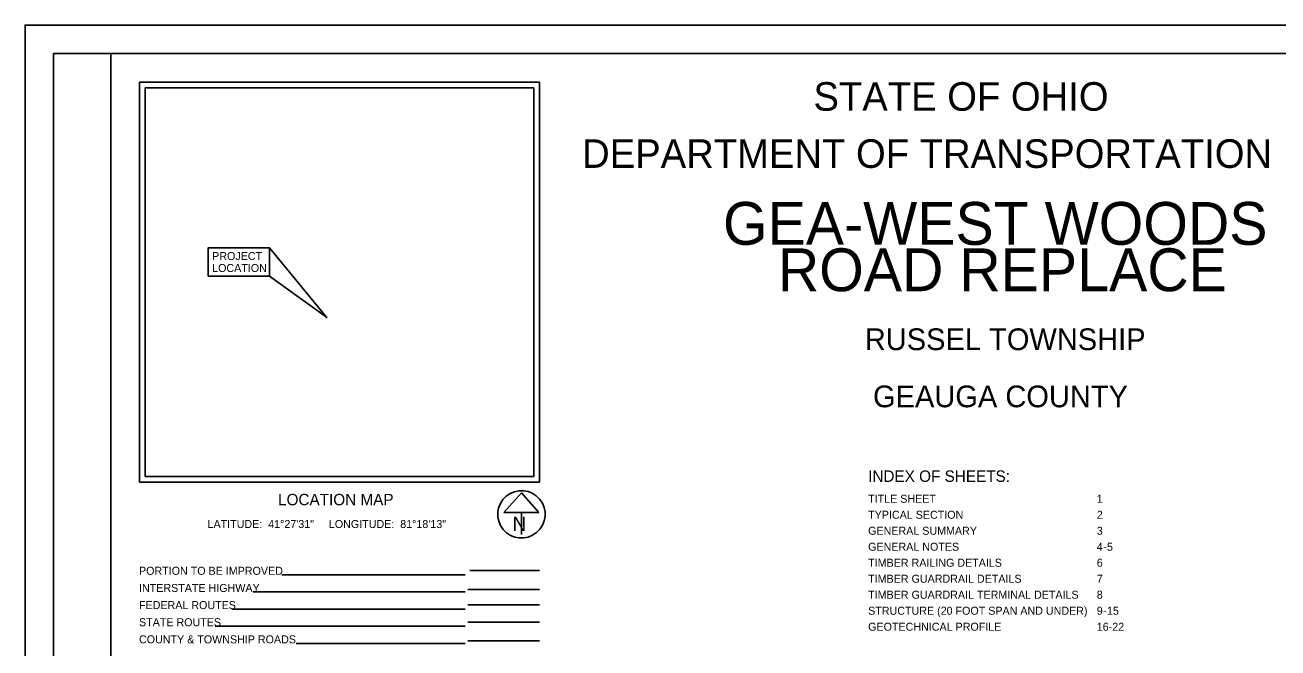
# Model space of a CAD drawing. Extents: x 0 to 81.5, y 0 to 35.2.
# Drawn here: x 0 to 21.92, y 11.1 to 22 of the extents above; entities that cross this region are included whole.
import ezdxf

# ---------------------------------------------------------------- set-up
doc = ezdxf.new("R2010")
doc.units = 0
for name, color, linetype in [('Default', 7, 'Continuous'), ('SH_Border', 7, 'Continuous'), ('SH_Cut_Line', 7, 'Continuous'), ('SH_Data', 7, 'Continuous'), ('SH_Text', 7, 'Continuous')]:
    doc.layers.add(name, color=color, linetype=linetype)

msp = doc.modelspace()

# ---------------------------------------------------------------- linework, layer by layer
at = {"layer": 'Default'}
for points in [[(3.204, 17.602), (4.276, 17.602), (4.276, 18.102), (3.204, 18.102)], [(4.276, 18.102), (5.277, 16.884), (4.276, 17.602)]]:
    msp.add_lwpolyline(points, close=True, dxfattribs=at)
at = {"layer": 'SH_Border'}
for points in [[(0.5, 21.5), (1.5, 21.5), (1.5, 0.5), (0.5, 0.5)], [(1.5, 21.5), (33.5, 21.5), (33.5, 0.5), (1.5, 0.5)]]:
    msp.add_lwpolyline(points, close=True, dxfattribs=at)
at = {"layer": 'SH_Cut_Line'}
msp.add_lwpolyline([(0, 0), (34, 0), (34, 22), (0, 22)], close=True, dxfattribs=at)
at = {"layer": 'SH_Data'}
for p, q in [((2, 21), (9, 21)), ((2, 21), (2, 14)), ((2.1, 20.9), (2.1, 14.1)), ((2.1, 20.9), (8.9, 20.9)), ((8.9, 20.9), (8.9, 14.1)), ((9, 21), (9, 14)), ((5.277, 16.9), (5.276, 16.868)), ((2.1, 14.1), (8.9, 14.1)), ((2.1, 14.1), (2.1, 14.1)), ((2, 14), (9, 14)), ((8.685, 13.809), (8.377, 13.468)), ((8.992, 13.468), (8.685, 13.809)), ((8.377, 13.468), (8.992, 13.468)), ((8.685, 13.468), (8.685, 13.081)), ((8.685, 13.435), (8.685, 13.435)), ((8.685, 13.435), (8.685, 13.435)), ((7.7, 12.377), (4.494, 12.377)), ((7.783, 12.455), (9, 12.455)), ((7.7, 12.077), (3.99, 12.077)), ((9, 12.121), (7.75, 12.121)), ((9, 11.849), (7.75, 11.849)), ((7.7, 11.777), (3.619, 11.777)), ((7.7, 11.477), (3.329, 11.477)), ((9, 11.549), (7.75, 11.549)), ((9, 11.222), (7.75, 11.222)), ((7.7, 11.177), (4.745, 11.177))]:
    msp.add_line(p, q, dxfattribs=at)
msp.add_arc((8.685, 13.435), 0.415, 129.7798, 129.7633, dxfattribs=at)

# ---------------------------------------------------------------- texts
at = {"layer": 'Default'}
for s, p in [('PROJECT', (3.274, 17.887)), ('LOCATION', (3.274, 17.677))]:
    msp.add_text(s, height=0.14, dxfattribs=at).set_placement(p)
at = {"layer": 'SH_Data'}
msp.add_text('N', height=0.25, dxfattribs=at).set_placement((8.529, 13.144))
at = {"layer": 'SH_Text'}
for s, height, p in [('STATE OF OHIO', 0.5, (13.795, 20.5)), ('DEPARTMENT OF TRANSPORTATION', 0.5, (9.747, 19.5)), ('GEA-WEST WOODS', 0.75, (12.212, 18.153)), ('ROAD REPLACE', 0.75, (13.171, 17.341)), ('RUSSEL TOWNSHIP', 0.38, (14.693, 16.31)), ('GEAUGA COUNTY', 0.38, (14.837, 15.31)), ('INDEX OF SHEETS:', 0.2, (14.752, 14.004)), ('LOCATION MAP', 0.2, (4.427, 13.594)), ('TITLE SHEET ', 0.14, (14.752, 13.638)), ('1', 0.14, (18.752, 13.638)), ('TYPICAL SECTION ', 0.14, (14.752, 13.358)), ('2', 0.14, (18.752, 13.358)), ('LATITUDE:  41°27\'31"     LONGITUDE:  81°18\'13"', 0.14, (3.193, 13.196)), ('GENERAL SUMMARY ', 0.14, (14.752, 13.078)), ('3', 0.14, (18.752, 13.078)), ('GENERAL NOTES ', 0.14, (14.752, 12.798)), ('4', 0.14, (18.752, 12.798)), ('5', 0.14, (18.931, 12.798)), ('-', 0.14, (18.863, 12.798)), ('PORTION TO BE IMPROVED', 0.14, (1.994, 12.377)), ('TIMBER RAILING DETAILS   ', 0.14, (14.752, 12.518)), ('6', 0.14, (18.752, 12.518)), ('TIMBER GUARDRAIL DETAILS ', 0.14, (14.752, 12.238)), ('7', 0.14, (18.752, 12.238)), ('INTERSTATE HIGHWAY', 0.14, (1.994, 12.077)), ('TIMBER GUARDRAIL TERMINAL DETAILS                  ', 0.14, (14.752, 11.958)), ('8', 0.14, (18.752, 11.958)), ('FEDERAL ROUTES', 0.14, (1.994, 11.777)), ('STATE ROUTES', 0.14, (1.994, 11.477)), ('STRUCTURE (20 FOOT SPAN AND UNDER) ', 0.14, (14.752, 11.678)), ('9', 0.14, (18.752, 11.678)), ('-', 0.14, (18.863, 11.678)), ('15', 0.14, (18.931, 11.678)), ('GEOTECHNICAL PROFILE ', 0.14, (14.752, 11.398)), ('16-22', 0.14, (18.752, 11.398)), ('COUNTY & TOWNSHIP ROADS', 0.14, (1.994, 11.177))]:
    msp.add_text(s, height=height, dxfattribs=at).set_placement(p)

doc.saveas('drawing.dxf')
